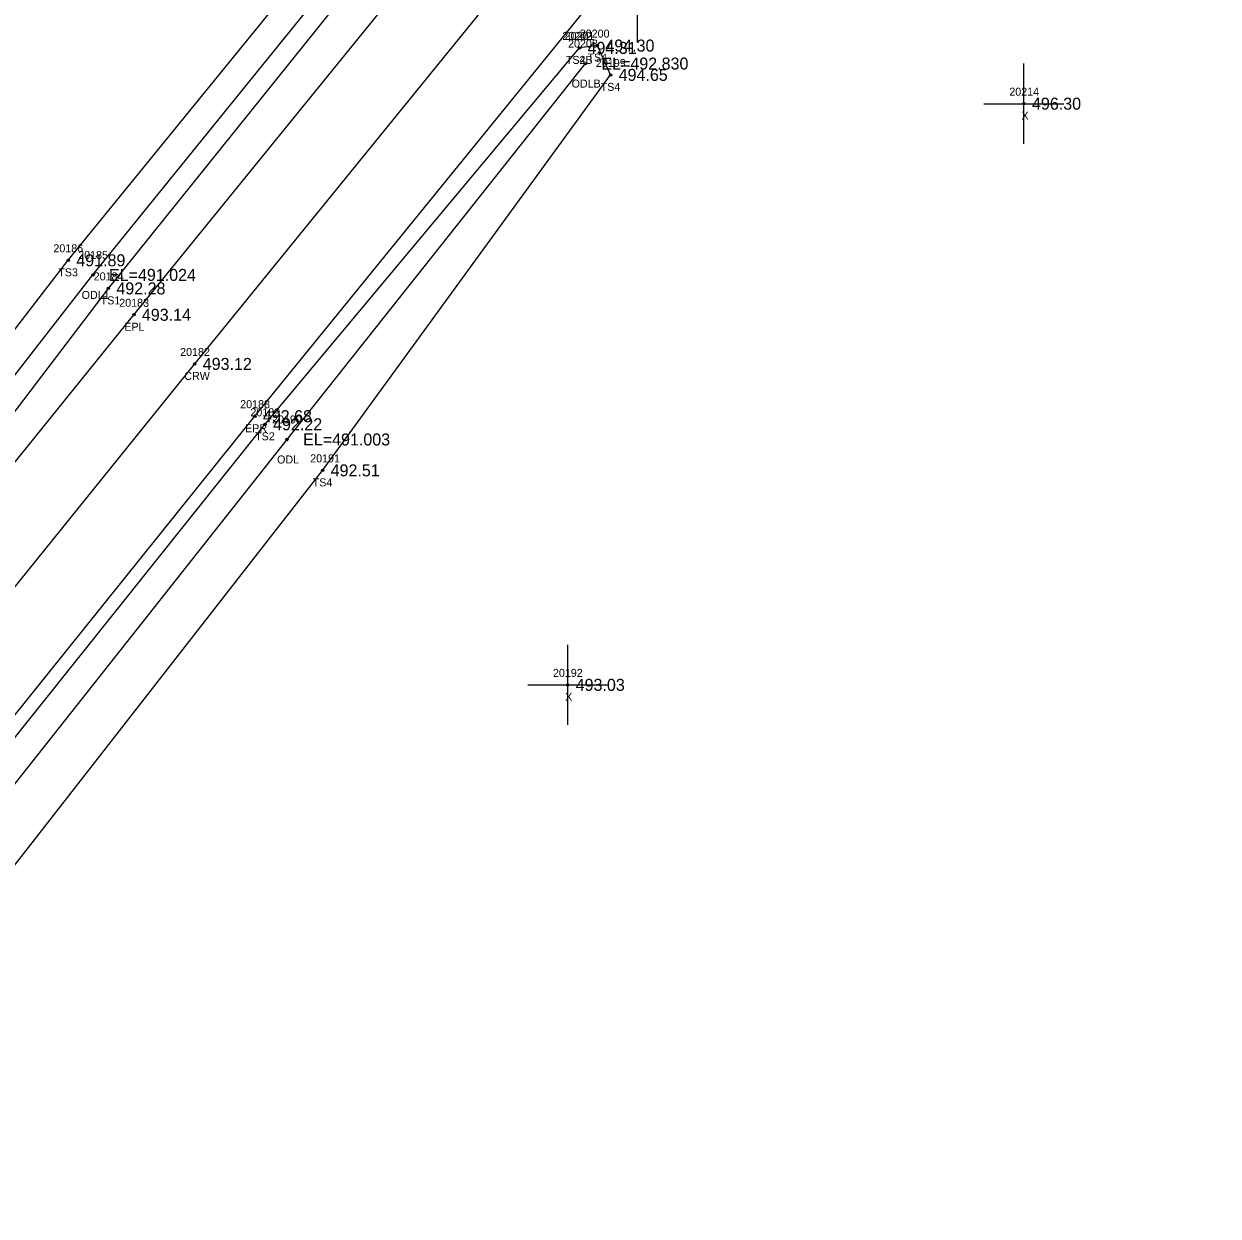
# Model space of a CAD drawing. Extents: x 1789565 to 1790548, y 909019 to 910194.
# Drawn here: x 1790354.5 to 1790503.8, y 909900.3 to 910049.3 of the extents above; entities that cross this region are included whole.
import ezdxf

# ---------------------------------------------------------------- set-up
doc = ezdxf.new("R2010")
doc.units = 0
for name, color, linetype in [('RD_DTM_BkLn1', 7, 'Continuous'), ('RD_DTM_BkLn2', 7, 'Continuous'), ('RD_DTM_BkLn_txCode', 7, 'Continuous'), ('RD_EX_H2O', 7, 'Continuous'), ('RD_EX_H2O_txCode', 7, 'Continuous'), ('RD_EX_Misc', 7, 'Continuous'), ('RD_EX_Misc_txCode', 7, 'Continuous'), ('RD_EX_Road', 7, 'Continuous'), ('RD_EX_Road_txCode', 7, 'Continuous'), ('RD_EX_TX_H2O_ELEV', 7, 'Continuous'), ('RD_EX_TX_Misc_ELEV', 7, 'Continuous'), ('RD_EX_TX_Road_ELEV', 7, 'Continuous'), ('RD_HC_Survey_ELEV', 7, 'Continuous'), ('RD_HC_Survey_txCode', 7, 'Continuous'), ('RD_SMD_Locator', 7, 'Continuous')]:
    doc.layers.add(name, color=color, linetype=linetype)

msp = doc.modelspace()

# ---------------------------------------------------------------- linework, layer by layer
at = {"layer": 'RD_DTM_BkLn1'}
msp.add_lwpolyline([(1790071.24, 909625.67), (1790132.78, 909702.56), (1790193.17, 909778.64), (1790254.11, 909855.13), (1790314.56, 909930.82), (1790375.87, 910006.79), (1790434.17, 910078.51), (1790495.95, 910153.23)], dxfattribs=at)
at = {"layer": 'RD_DTM_BkLn2'}
for points in [[(1790181.61, 909789.75), (1790181.34, 909795.67), (1790239.02, 909867.4), (1790301.11, 909943.25), (1790360.06, 910019.74), (1790418.43, 910091.45), (1790480.61, 910166.7)], [(1790060.69, 909634.71), (1790061.47, 909641.75), (1790119.6, 909713.74), (1790183.37, 909787.88), (1790244.44, 909862.78), (1790306.19, 909938.82), (1790365.07, 910016.23), (1790422.97, 910088.22), (1790484.03, 910163.43)], [(1790081.67, 909617.32), (1790086.3, 909617), (1790143.13, 909693.7), (1790202.72, 909770.52), (1790263.97, 909846.87), (1790323.52, 909922.76), (1790384.66, 909999.25), (1790423.96, 910046.28)], [(1790092.97, 909612.92), (1790097.34, 909612.95), (1790152.91, 909684.97), (1790214.4, 909761.5), (1790270.76, 909842.42), (1790331.58, 909916.3), (1790391.85, 909993.49), (1790427.85, 910042.91), (1790426.19, 910046.57), (1790423.96, 910046.28)]]:
    msp.add_lwpolyline(points, dxfattribs=at)
at = {"layer": 'RD_EX_H2O'}
for points in [[(1790181.61, 909789.75), (1790242.2, 909864.6), (1790303.39, 909941.16), (1790363.14, 910017.91), (1790421.33, 910089.83), (1790482.18, 910165.24)], [(1790092.97, 909612.92), (1790147.38, 909690.09), (1790206.86, 909767.79), (1790266.43, 909845.39), (1790326.38, 909920.19), (1790387.41, 909997.35), (1790424.69, 910044.32)]]:
    msp.add_lwpolyline(points, dxfattribs=at)
at = {"layer": 'RD_EX_Misc'}
for p, q in [((1790431.19, 910046.97), (1790431.19, 910056.97)), ((1790479.51, 910034.31), (1790479.51, 910044.31)), ((1790474.51, 910039.31), (1790484.51, 910039.31)), ((1790422.48, 909961.69), (1790422.48, 909971.69)), ((1790417.48, 909966.69), (1790427.48, 909966.69))]:
    msp.add_line(p, q, dxfattribs=at)
at = {"layer": 'RD_EX_Road'}
for points in [[(1790071.29, 909625.64), (1790063.58, 909631.76), (1790124.98, 909708.45), (1790186, 909785.5), (1790246.28, 909861.1), (1790307.38, 909937.59), (1790368.26, 910012.93), (1790426.56, 910084.73), (1790488.45, 910159.81)], [(1790071.25, 909625.72), (1790078.96, 909619.74), (1790139.76, 909696.36), (1790200.89, 909772.13), (1790261.64, 909848.6), (1790322.1, 909924.01), (1790383.38, 910000.26), (1790441.69, 910072.01), (1790503.77, 910147.05)]]:
    msp.add_lwpolyline(points, dxfattribs=at)
at = {"layer": 'RD_SMD_Locator'}
for centre in [(1790423.96, 910046.28), (1790423.96, 910046.28), (1790426.19, 910046.57), (1790424.69, 910044.32), (1790427.85, 910042.91), (1790479.51, 910039.31), (1790360.06, 910019.74), (1790363.14, 910017.91), (1790365.07, 910016.23), (1790368.26, 910012.93), (1790375.87, 910006.79), (1790383.38, 910000.26), (1790384.66, 909999.25), (1790387.41, 909997.35), (1790391.85, 909993.49), (1790422.48, 909966.69)]:
    msp.add_circle(centre, 0.15, dxfattribs=at)

# ---------------------------------------------------------------- texts
at = {"layer": 'RD_DTM_BkLn_txCode'}
for s, p in [('20202', (1790421.81, 910047.28)), ('20201', (1790422.09, 910047.28)), ('20200', (1790423.99, 910047.57)), ('TS4B', (1790422.25, 910044.28)), ('TS2B', (1790422.25, 910044.28)), ('TS4', (1790424.95, 910044.57)), ('20199', (1790426.01, 910043.91)), ('TS4', (1790426.6, 910040.91)), ('20186', (1790358.2, 910020.74)), ('TS3', (1790358.81, 910017.74)), ('20184', (1790363.24, 910017.23)), ('TS1', (1790364.11, 910014.23)), ('20189', (1790382.82, 910000.25)), ('TS2', (1790383.41, 909997.25)), ('20191', (1790390.3, 909994.49)), ('TS4', (1790390.61, 909991.49))]:
    msp.add_text(s, height=1, dxfattribs=at).set_placement(p)
at = {"layer": 'RD_EX_H2O_txCode'}
for s, p in [('20203', (1790422.53, 910046.32)), ('ODLB', (1790422.97, 910041.32)), ('20185', (1790361.3, 910019.91)), ('ODL1', (1790361.73, 910014.91)), ('20190', (1790385.53, 909999.35)), ('ODL', (1790386.16, 909994.35))]:
    msp.add_text(s, height=1, dxfattribs=at).set_placement(p)
at = {"layer": 'RD_EX_Misc_txCode'}
for s, p in [('20214', (1790477.68, 910040.31)), ('X', (1790479.2, 910037.31)), ('20192', (1790420.64, 909967.69)), ('X', (1790422.16, 909964.69))]:
    msp.add_text(s, height=1, dxfattribs=at).set_placement(p)
at = {"layer": 'RD_EX_Road_txCode'}
for s, p in [('20183', (1790366.43, 910013.93)), ('EPL', (1790367.06, 910010.93)), ('20188', (1790381.55, 910001.26)), ('EPR', (1790382.15, 909998.26))]:
    msp.add_text(s, height=1, dxfattribs=at).set_placement(p)
at = {"layer": 'RD_EX_TX_H2O_ELEV'}
for s, p in [('EL=492.830', (1790426.69, 910043.57)), ('EL=491.024', (1790365.14, 910017.16)), ('EL=491.003', (1790389.41, 909996.6))]:
    msp.add_text(s, height=1.5, dxfattribs=at).set_placement(p)
at = {"layer": 'RD_EX_TX_Misc_ELEV'}
for s, p in [('494.30', (1790427.19, 910045.82)), ('494.31', (1790424.96, 910045.53)), ('494.31', (1790424.96, 910045.53)), ('494.65', (1790428.85, 910042.16)), ('496.30', (1790480.51, 910038.56)), ('491.89', (1790361.06, 910018.99)), ('492.28', (1790366.07, 910015.48)), ('492.22', (1790385.66, 909998.5)), ('492.51', (1790392.85, 909992.74)), ('493.03', (1790423.48, 909965.94))]:
    msp.add_text(s, height=1.5, dxfattribs=at).set_placement(p)
at = {"layer": 'RD_EX_TX_Road_ELEV'}
for s, p in [('493.14', (1790369.26, 910012.18)), ('492.68', (1790384.38, 909999.51))]:
    msp.add_text(s, height=1.5, dxfattribs=at).set_placement(p)
at = {"layer": 'RD_HC_Survey_ELEV'}
msp.add_text('493.12', height=1.5, dxfattribs=at).set_placement((1790376.87, 910006.04))
at = {"layer": 'RD_HC_Survey_txCode'}
for s, p in [('20182', (1790374.04, 910007.79)), ('CRW', (1790374.56, 910004.79))]:
    msp.add_text(s, height=1, dxfattribs=at).set_placement(p)

doc.saveas('drawing.dxf')
